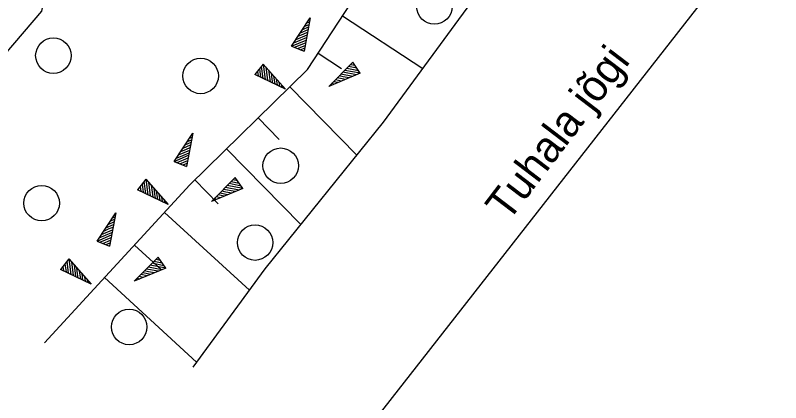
# Model space of a CAD drawing. Extents: x 554947 to 555436, y 6564938 to 6565792.
# Drawn here: x 555286.36 to 555303.63, y 6565104.61 to 6565113.35 of the extents above; entities that cross this region are included whole.
import ezdxf

# ---------------------------------------------------------------- set-up
doc = ezdxf.new("R2010")
doc.units = 0
for name, color, linetype in [('HALJASTUS', 7, 'Continuous'), ('PIIR', 7, 'Continuous'), ('RELJEEF', 7, 'Continuous'), ('VEEKOGU', 7, 'Continuous')]:
    doc.layers.add(name, color=color, linetype=linetype)

msp = doc.modelspace()

# ---------------------------------------------------------------- linework, layer by layer
at = {"layer": 'HALJASTUS'}
msp.add_lwpolyline([(555284.462, 6565140.172), (555288.412, 6565133.905), (555290.653, 6565126.338), (555287.948, 6565118.22), (555286.947, 6565113.44), (555283.151, 6565108.996), (555281.188, 6565105.176)], dxfattribs=at)
for centre in [(555295.813, 6565113.546), (555287.218, 6565112.438), (555290.54, 6565111.98), (555292.346, 6565109.956), (555286.953, 6565109.113), (555291.768, 6565108.222), (555288.927, 6565106.319)]:
    msp.add_circle(centre, 0.4, dxfattribs=at)
at = {"layer": 'PIIR'}
msp.add_lwpolyline([(555293.54, 6565286.23), (555256.63, 6565245.54), (555254.61, 6565228.5), (555255.75, 6565226.79), (555261.42, 6565218.27), (555289.11, 6565186.6), (555315.28, 6565149.09), (555315.73, 6565134.86), (555310.07, 6565124.47), (555303.59, 6565115.89), (555291.54, 6565100.48), (555288.85, 6565092.31), (555275.41, 6565088.83), (555273.15, 6565087.34), (555239.11, 6565139), (555231.12, 6565150.64), (555225.89, 6565157.13), (555173.21, 6565166.35), (555173.84, 6565168.77), (555191.64, 6565237.48), (555195.28, 6565271.63)], dxfattribs=at)
at = {"layer": 'RELJEEF'}
for p, q in [((555292.592, 6565112.651), (555293.012, 6565113.291)), ((555293.012, 6565113.291), (555292.872, 6565112.536)), ((555292.987, 6565113.251), (555293.007, 6565113.261)), ((555293.738, 6565113.333), (555295.549, 6565112.147)), ((555292.842, 6565113.026), (555292.972, 6565113.086)), ((555292.887, 6565113.101), (555292.987, 6565113.141)), ((555292.937, 6565113.176), (555292.997, 6565113.201)), ((555292.692, 6565112.801), (555292.942, 6565112.906)), ((555292.742, 6565112.876), (555292.867, 6565112.931)), ((555292.792, 6565112.951), (555292.962, 6565113.026)), ((555292.867, 6565112.931), (555292.952, 6565112.966)), ((555292.592, 6565112.651), (555292.917, 6565112.791)), ((555292.642, 6565112.726), (555292.927, 6565112.846)), ((555292.657, 6565112.626), (555292.907, 6565112.731)), ((555292.592, 6565112.651), (555292.872, 6565112.536)), ((555292.592, 6565112.651), (555292.592, 6565112.651)), ((555292.722, 6565112.596), (555292.897, 6565112.671)), ((555292.792, 6565112.571), (555292.887, 6565112.611)), ((555292.857, 6565112.546), (555292.872, 6565112.551)), ((555293.19, 6565112.497), (555293.72, 6565112.15)), ((555291.95, 6565112.25), (555291.765, 6565112.01)), ((555291.905, 6565112.195), (555291.94, 6565111.925)), ((555291.95, 6565112.25), (555292.455, 6565111.68)), ((555291.95, 6565112.25), (555291.995, 6565111.9)), ((555291.95, 6565112.25), (555291.95, 6565112.25)), ((555292.01, 6565112.185), (555292.05, 6565111.875)), ((555293.43, 6565111.745), (555293.97, 6565112.29)), ((555294.06, 6565112.155), (555293.875, 6565112.19)), ((555294.02, 6565112.215), (555293.92, 6565112.235)), ((555293.98, 6565112.275), (555293.96, 6565112.275)), ((555294.14, 6565112.04), (555293.97, 6565112.29)), ((555292.455, 6565111.68), (555291.765, 6565112.01)), ((555291.775, 6565112.025), (555291.78, 6565112.005)), ((555291.82, 6565112.08), (555291.835, 6565111.98)), ((555291.865, 6565112.14), (555291.89, 6565111.955)), ((555292.07, 6565112.115), (555292.105, 6565111.85)), ((555292.13, 6565112.05), (555292.145, 6565111.91)), ((555294.14, 6565112.04), (555293.43, 6565111.745)), ((555293.97, 6565111.97), (555293.705, 6565112.02)), ((555294.055, 6565112.005), (555293.75, 6565112.065)), ((555294.14, 6565112.04), (555293.79, 6565112.105)), ((555294.1, 6565112.095), (555293.835, 6565112.15)), ((555294.14, 6565112.04), (555294.14, 6565112.04)), ((555292.145, 6565111.91), (555292.16, 6565111.82)), ((555292.185, 6565111.98), (555292.215, 6565111.795)), ((555292.245, 6565111.915), (555292.265, 6565111.77)), ((555292.305, 6565111.845), (555292.32, 6565111.745)), ((555293.64, 6565111.83), (555293.535, 6565111.85)), ((555293.72, 6565111.865), (555293.58, 6565111.895)), ((555293.805, 6565111.9), (555293.62, 6565111.935)), ((555293.755, 6565111.96), (555293.665, 6565111.98)), ((555293.89, 6565111.935), (555293.755, 6565111.96)), ((555292.365, 6565111.78), (555292.375, 6565111.715)), ((555292.425, 6565111.71), (555292.43, 6565111.69)), ((555292.55, 6565111.736), (555294.062, 6565110.195)), ((555293.47, 6565111.76), (555293.455, 6565111.765)), ((555293.555, 6565111.795), (555293.495, 6565111.81)), ((555291.836, 6565111.036), (555292.315, 6565110.548)), ((555289.944, 6565110.053), (555290.364, 6565110.693)), ((555290.364, 6565110.693), (555290.224, 6565109.938)), ((555290.339, 6565110.653), (555290.359, 6565110.663)), ((555290.194, 6565110.428), (555290.324, 6565110.488)), ((555290.239, 6565110.503), (555290.339, 6565110.543)), ((555290.289, 6565110.578), (555290.349, 6565110.603)), ((555290.044, 6565110.203), (555290.294, 6565110.308)), ((555290.094, 6565110.278), (555290.219, 6565110.333)), ((555290.144, 6565110.353), (555290.314, 6565110.428)), ((555290.219, 6565110.333), (555290.304, 6565110.368)), ((555291.123, 6565110.335), (555292.798, 6565108.627)), ((555289.944, 6565110.053), (555290.269, 6565110.193)), ((555289.994, 6565110.128), (555290.279, 6565110.248)), ((555290.009, 6565110.028), (555290.259, 6565110.133)), ((555289.944, 6565110.053), (555290.224, 6565109.938)), ((555289.944, 6565110.053), (555289.944, 6565110.053)), ((555290.074, 6565109.998), (555290.249, 6565110.073)), ((555290.144, 6565109.973), (555290.239, 6565110.013)), ((555290.209, 6565109.948), (555290.224, 6565109.953)), ((555289.303, 6565109.652), (555289.118, 6565109.413)), ((555289.258, 6565109.598), (555289.293, 6565109.328)), ((555289.303, 6565109.652), (555289.808, 6565109.083)), ((555289.303, 6565109.652), (555289.348, 6565109.303)), ((555289.303, 6565109.652), (555289.303, 6565109.652)), ((555289.363, 6565109.588), (555289.403, 6565109.277)), ((555290.409, 6565109.635), (555290.936, 6565109.098)), ((555290.782, 6565109.147), (555291.322, 6565109.692)), ((555291.412, 6565109.558), (555291.227, 6565109.593)), ((555291.372, 6565109.617), (555291.272, 6565109.638)), ((555291.332, 6565109.678), (555291.312, 6565109.678)), ((555291.492, 6565109.442), (555291.322, 6565109.692)), ((555289.808, 6565109.083), (555289.118, 6565109.413)), ((555289.128, 6565109.428), (555289.133, 6565109.407)), ((555289.173, 6565109.482), (555289.188, 6565109.383)), ((555289.218, 6565109.543), (555289.243, 6565109.357)), ((555289.423, 6565109.518), (555289.458, 6565109.253)), ((555289.483, 6565109.453), (555289.498, 6565109.312)), ((555291.492, 6565109.442), (555290.782, 6565109.147)), ((555291.322, 6565109.373), (555291.057, 6565109.423)), ((555291.407, 6565109.407), (555291.102, 6565109.468)), ((555291.492, 6565109.442), (555291.142, 6565109.508)), ((555291.452, 6565109.498), (555291.187, 6565109.553)), ((555291.492, 6565109.442), (555291.492, 6565109.442)), ((555289.498, 6565109.312), (555289.513, 6565109.223)), ((555289.538, 6565109.383), (555289.568, 6565109.197)), ((555289.598, 6565109.317), (555289.618, 6565109.173)), ((555289.658, 6565109.248), (555289.673, 6565109.147)), ((555290.992, 6565109.232), (555290.887, 6565109.253)), ((555291.072, 6565109.268), (555290.932, 6565109.298)), ((555291.157, 6565109.303), (555290.972, 6565109.338)), ((555291.107, 6565109.362), (555291.017, 6565109.383)), ((555291.242, 6565109.338), (555291.107, 6565109.362)), ((555289.718, 6565109.183), (555289.728, 6565109.117)), ((555289.778, 6565109.112), (555289.783, 6565109.093)), ((555290.822, 6565109.163), (555290.807, 6565109.168)), ((555290.907, 6565109.197), (555290.847, 6565109.213)), ((555288.204, 6565108.257), (555288.624, 6565108.897)), ((555288.624, 6565108.897), (555288.484, 6565108.142)), ((555289.726, 6565108.904), (555291.639, 6565107.146)), ((555288.499, 6565108.707), (555288.599, 6565108.747)), ((555288.549, 6565108.782), (555288.609, 6565108.807)), ((555288.599, 6565108.857), (555288.619, 6565108.867)), ((555288.404, 6565108.557), (555288.574, 6565108.632)), ((555288.454, 6565108.632), (555288.584, 6565108.692)), ((555288.479, 6565108.537), (555288.564, 6565108.572)), ((555288.204, 6565108.257), (555288.529, 6565108.397)), ((555288.254, 6565108.332), (555288.539, 6565108.452)), ((555288.304, 6565108.407), (555288.554, 6565108.512)), ((555288.354, 6565108.482), (555288.479, 6565108.537)), ((555288.204, 6565108.257), (555288.484, 6565108.142)), ((555288.204, 6565108.257), (555288.204, 6565108.257)), ((555288.269, 6565108.232), (555288.519, 6565108.337)), ((555288.334, 6565108.202), (555288.509, 6565108.277)), ((555288.404, 6565108.177), (555288.499, 6565108.217)), ((555288.469, 6565108.152), (555288.484, 6565108.157)), ((555289.05, 6565108.168), (555289.648, 6565107.618)), ((555287.563, 6565107.856), (555287.378, 6565107.616)), ((555287.563, 6565107.856), (555288.068, 6565107.286)), ((555287.563, 6565107.856), (555287.608, 6565107.506)), ((555287.563, 6565107.856), (555287.563, 6565107.856)), ((555289.042, 6565107.351), (555289.582, 6565107.896)), ((555289.592, 6565107.881), (555289.572, 6565107.881)), ((555289.752, 6565107.646), (555289.582, 6565107.896)), ((555287.433, 6565107.686), (555287.448, 6565107.586)), ((555287.478, 6565107.746), (555287.503, 6565107.561)), ((555287.518, 6565107.801), (555287.553, 6565107.531)), ((555287.623, 6565107.791), (555287.663, 6565107.481)), ((555287.683, 6565107.721), (555287.718, 6565107.456)), ((555289.752, 6565107.646), (555289.402, 6565107.711)), ((555289.712, 6565107.701), (555289.447, 6565107.756)), ((555289.672, 6565107.761), (555289.487, 6565107.796)), ((555289.632, 6565107.821), (555289.532, 6565107.841)), ((555288.068, 6565107.286), (555287.378, 6565107.616)), ((555287.388, 6565107.631), (555287.393, 6565107.611)), ((555287.743, 6565107.656), (555287.758, 6565107.516)), ((555287.758, 6565107.516), (555287.773, 6565107.426)), ((555287.798, 6565107.586), (555287.828, 6565107.401)), ((555287.858, 6565107.521), (555287.878, 6565107.376)), ((555289.752, 6565107.646), (555289.042, 6565107.351)), ((555289.417, 6565107.506), (555289.232, 6565107.541)), ((555289.367, 6565107.566), (555289.277, 6565107.586)), ((555289.582, 6565107.576), (555289.317, 6565107.626)), ((555289.667, 6565107.611), (555289.362, 6565107.671)), ((555289.502, 6565107.541), (555289.367, 6565107.566)), ((555289.752, 6565107.646), (555289.752, 6565107.646)), ((555287.918, 6565107.451), (555287.933, 6565107.351)), ((555287.978, 6565107.386), (555287.988, 6565107.321)), ((555288.373, 6565107.432), (555290.449, 6565105.524)), ((555289.082, 6565107.366), (555289.067, 6565107.371)), ((555289.167, 6565107.401), (555289.107, 6565107.416)), ((555289.252, 6565107.436), (555289.147, 6565107.456)), ((555289.332, 6565107.471), (555289.192, 6565107.501)), ((555288.038, 6565107.316), (555288.043, 6565107.296))]:
    msp.add_line(p, q, dxfattribs=at)
msp.add_lwpolyline([(555287.02, 6565105.959), (555290.299, 6565109.527), (555292.947, 6565112.125), (555299.831, 6565122.632)], dxfattribs=at)
at = {"layer": 'VEEKOGU'}
msp.add_lwpolyline([(555290.37, 6565105.416), (555291.997, 6565107.634), (555294.663, 6565110.939), (555303.207, 6565122.581)], dxfattribs=at)

# ---------------------------------------------------------------- texts
msp.add_text('Tuhala jõgi', height=0.7, rotation=52.6977, dxfattribs=at).set_placement((555297.477, 6565108.668))

doc.saveas('drawing.dxf')
